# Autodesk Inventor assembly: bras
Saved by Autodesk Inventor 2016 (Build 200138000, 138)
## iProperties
Created: 2013-10
Part Number: bras
Material: Générique
Document SubType Name: Assembly
Designer: Bruno
Author: Bruno
Sending System: SolidWorks 2013
Last Author: christophe
Last Saved: 2014-02-15
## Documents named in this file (6)
- D:\Cours\Systèmes\SI\Robot Haptique\Documentations_pedagogique\Modèle solidworks\Réel\bras.iam
- D:\Cours\Systèmes\SI\Robot Haptique\Documentations_pedagogique\Modèle solidworks\Réel\bras.ipt
- D:\Cours\Systèmes\SI\Robot Haptique\Documentations_pedagogique\Modèle solidworks\Réel\AXE BRAS.ipt
- D:\Cours\Systèmes\SI\Robot Haptique\Documentations_pedagogique\Modèle solidworks\Réel\palier bras.ipt
- D:\Cours\Systèmes\SI\Robot Haptique\Documentations_pedagogique\Modèle solidworks\Réel\Ressort cable.ipt
- D:\Cours\Systèmes\SI\Robot Haptique\Documentations_pedagogique\Modèle solidworks\Réel\FIXATION CABLE.ipt
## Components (6 placed, 5 different names)
1. bras:1
2. AXE BRAS:1
3. palier bras:1
4. palier bras:2
5. Ressort cable:1
6. FIXATION CABLE:1
